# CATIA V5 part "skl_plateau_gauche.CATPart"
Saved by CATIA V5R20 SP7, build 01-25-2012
Part number: skl_plateau_gauche
Publications: "Point.K", "Point.H", "Droite.1", "Droite.2", "Droite.3"
Bounding box of the stored display mesh (mm): x -150 to -150, y 0 to 30, z 0 to 20
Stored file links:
  D:\IFMA\COURS\2A\projet balance IAO\catia\skl_plateau_gauche.CATPart
  D:\IFMA\COURS\2A\projet balance IAO\catia\Skl_projet_balance.CATProduct
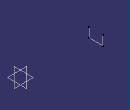
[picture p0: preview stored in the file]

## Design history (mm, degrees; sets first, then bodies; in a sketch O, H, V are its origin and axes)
Set1
  Point1 "Point.K": linked copy from another document
  Point2 "Point.H": linked copy from another document
  Plane1 "Plan_plateau_gauche": linked copy from another document
  Point3 "Point.F": linked copy from another document
Body1 (main body)
  Point4 "Point.K": stored without definition
  Point5 "Point.H": stored without definition
  Line1: type PtPt, FirstPoint Point1, SecondPoint Point2
  Line2: type PtDir, RefPoint Point1, Direction xy-plane, Start 0, End 20
  Line3: type PtDir, RefPoint Point2, Direction xy-plane, Start 0, End 20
